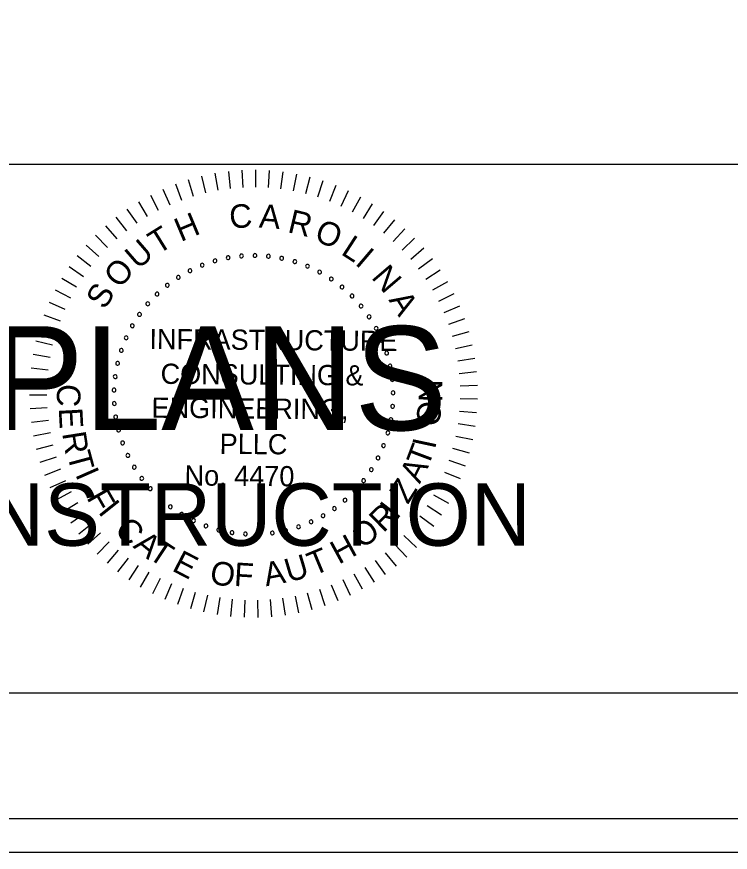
# Model space of a CAD drawing. Extents: x 967 to 1326, y 964 to 3704.
# Drawn here: x 1189.3 to 1212.88, y 3203.72 to 3231.36 of the extents above; entities that cross this region are included whole.
import ezdxf

# ---------------------------------------------------------------- set-up
doc = ezdxf.new("R2010")
doc.units = 0
for name, color, linetype in [('RD_SHT_Bndy', 7, 'Continuous'), ('RD_SHT_IplotShp', 7, 'Continuous'), ('RD_SHT_Misc1', 7, 'Continuous'), ('RD_SHT_Misc2', 7, 'Continuous'), ('RD_XS_TX_Station', 7, 'Continuous')]:
    doc.layers.add(name, color=color, linetype=linetype)

msp = doc.modelspace()

# ---------------------------------------------------------------- linework, layer by layer
at = {"layer": 'RD_SHT_Bndy'}
for p, q in [((996.114, 3226.486), (1323.886, 3226.486)), ((1323.886, 3208.983), (996.114, 3208.983))]:
    msp.add_line(p, q, dxfattribs=at)
at = {"layer": 'RD_SHT_IplotShp'}
for points in [[(967.409, 3203.72), (1326.285, 3203.72), (1326.285, 3423.72), (967.409, 3423.72)], [(988.525, 3204.84), (1326.285, 3204.84), (1326.285, 3422.6), (988.525, 3422.6)]]:
    msp.add_lwpolyline(points, close=True, dxfattribs=at)
at = {"layer": 'RD_SHT_Misc1'}
for p, q in [((1195.846, 3226.181), (1195.945, 3225.62)), ((1196.292, 3226.245), (1196.357, 3225.68)), ((1196.742, 3226.282), (1196.772, 3225.714)), ((1197.194, 3226.292), (1197.189, 3225.723)), ((1197.645, 3226.274), (1197.606, 3225.706)), ((1198.094, 3226.228), (1198.02, 3225.664)), ((1198.54, 3226.156), (1198.432, 3225.596)), ((1194.968, 3225.971), (1195.134, 3225.427)), ((1195.403, 3226.09), (1195.536, 3225.536)), ((1198.98, 3226.056), (1198.838, 3225.504)), ((1199.414, 3225.929), (1199.238, 3225.387)), ((1194.122, 3225.656), (1194.353, 3225.136)), ((1194.54, 3225.827), (1194.739, 3225.293)), ((1199.839, 3225.777), (1199.63, 3225.246)), ((1200.253, 3225.598), (1200.013, 3225.082)), ((1193.715, 3225.461), (1193.978, 3224.956)), ((1200.656, 3225.395), (1200.385, 3224.894)), ((1193.321, 3225.241), (1193.614, 3224.752)), ((1201.047, 3225.167), (1200.745, 3224.684)), ((1192.94, 3224.997), (1193.263, 3224.528)), ((1201.422, 3224.917), (1201.092, 3224.453)), ((1192.576, 3224.731), (1192.926, 3224.282)), ((1201.781, 3224.643), (1201.424, 3224.2)), ((1192.228, 3224.443), (1192.605, 3224.016)), ((1202.124, 3224.349), (1201.739, 3223.928)), ((1191.899, 3224.134), (1192.301, 3223.731)), ((1202.447, 3224.034), (1202.038, 3223.638)), ((1191.589, 3223.805), (1192.015, 3223.428)), ((1202.751, 3223.7), (1202.318, 3223.329)), ((1191.299, 3223.459), (1191.748, 3223.108)), ((1191.032, 3223.095), (1191.501, 3222.772)), ((1203.034, 3223.348), (1202.579, 3223.004)), ((1203.294, 3222.979), (1202.82, 3222.664)), ((1190.787, 3222.716), (1191.274, 3222.422)), ((1203.532, 3222.595), (1203.04, 3222.31)), ((1190.565, 3222.323), (1191.07, 3222.059)), ((1203.746, 3222.198), (1203.237, 3221.943)), ((1190.368, 3221.916), (1190.888, 3221.684)), ((1203.936, 3221.788), (1203.412, 3221.564)), ((1190.196, 3221.499), (1190.729, 3221.299)), ((1204.1, 3221.367), (1203.563, 3221.176)), ((1190.05, 3221.072), (1190.594, 3220.905)), ((1204.238, 3220.937), (1203.691, 3220.779)), ((1189.93, 3220.636), (1190.484, 3220.503)), ((1204.349, 3220.5), (1203.794, 3220.375)), ((1189.837, 3220.195), (1190.398, 3220.095)), ((1204.434, 3220.056), (1203.872, 3219.966)), ((1189.771, 3219.748), (1190.337, 3219.683)), ((1204.491, 3219.608), (1203.925, 3219.552)), ((1189.732, 3219.298), (1190.301, 3219.267)), ((1204.522, 3219.158), (1203.953, 3219.137)), ((1189.721, 3218.847), (1190.29, 3218.851)), ((1204.524, 3218.706), (1203.955, 3218.72)), ((1189.737, 3218.396), (1190.306, 3218.434)), ((1204.499, 3218.256), (1203.932, 3218.304)), ((1189.781, 3217.946), (1190.346, 3218.019)), ((1204.447, 3217.807), (1203.884, 3217.89)), ((1189.852, 3217.5), (1190.412, 3217.608)), ((1204.367, 3217.363), (1203.81, 3217.479)), ((1189.951, 3217.06), (1190.502, 3217.201)), ((1204.261, 3216.924), (1203.712, 3217.074)), ((1190.076, 3216.626), (1190.617, 3216.8)), ((1204.128, 3216.492), (1203.589, 3216.676)), ((1190.227, 3216.2), (1190.757, 3216.408)), ((1203.969, 3216.07), (1203.442, 3216.286)), ((1190.403, 3215.785), (1190.92, 3216.024)), ((1203.784, 3215.658), (1203.271, 3215.906)), ((1190.605, 3215.381), (1191.106, 3215.651)), ((1203.574, 3215.258), (1203.078, 3215.537)), ((1190.831, 3214.99), (1191.315, 3215.291)), ((1203.341, 3214.871), (1202.862, 3215.18)), ((1191.081, 3214.614), (1191.545, 3214.943)), ((1203.085, 3214.5), (1202.626, 3214.837)), ((1191.353, 3214.253), (1191.796, 3214.61)), ((1202.806, 3214.145), (1202.368, 3214.509)), ((1191.646, 3213.91), (1192.067, 3214.293)), ((1191.96, 3213.585), (1192.356, 3213.994)), ((1202.506, 3213.807), (1202.092, 3214.197)), ((1192.293, 3213.28), (1192.664, 3213.712)), ((1202.186, 3213.488), (1201.796, 3213.903)), ((1192.644, 3212.996), (1192.988, 3213.45)), ((1201.847, 3213.19), (1201.484, 3213.628)), ((1193.011, 3212.734), (1193.327, 3213.208)), ((1201.119, 3212.657), (1200.811, 3213.136)), ((1201.491, 3212.912), (1201.155, 3213.372)), ((1193.394, 3212.495), (1193.68, 3212.987)), ((1200.731, 3212.425), (1200.453, 3212.922)), ((1193.791, 3212.279), (1194.047, 3212.788)), ((1194.2, 3212.088), (1194.424, 3212.612)), ((1200.331, 3212.217), (1200.083, 3212.73)), ((1194.62, 3211.923), (1194.812, 3212.459)), ((1195.05, 3211.783), (1195.208, 3212.33)), ((1199.063, 3211.745), (1198.913, 3212.295)), ((1199.495, 3211.877), (1199.312, 3212.416)), ((1199.918, 3212.034), (1199.702, 3212.561)), ((1195.487, 3211.67), (1195.612, 3212.225)), ((1195.93, 3211.584), (1196.021, 3212.146)), ((1196.377, 3211.524), (1196.434, 3212.091)), ((1196.828, 3211.493), (1196.85, 3212.062)), ((1197.279, 3211.488), (1197.267, 3212.058)), ((1197.73, 3211.512), (1197.683, 3212.079)), ((1198.179, 3211.562), (1198.097, 3212.126)), ((1198.624, 3211.64), (1198.508, 3212.198))]:
    msp.add_line(p, q, dxfattribs=at)
for centre, start, end in [((1196.285, 3223.388), 10.6038, 190.6038), ((1196.285, 3223.388), 190.6038, 10.6038), ((1196.727, 3223.447), 5.0653, 185.0653), ((1196.727, 3223.447), 185.0653, 5.0653), ((1197.172, 3223.464), 359.5268, 179.5268), ((1197.172, 3223.464), 179.5268, 359.5268), ((1197.617, 3223.438), 173.9884, 353.9884), ((1197.617, 3223.438), 353.9884, 173.9884), ((1198.057, 3223.369), 168.4499, 348.4499), ((1198.057, 3223.369), 348.4499, 168.4499), ((1195.429, 3223.142), 21.6807, 201.6807), ((1195.429, 3223.142), 201.6807, 21.6807), ((1195.851, 3223.285), 16.1422, 196.1422), ((1195.851, 3223.285), 196.1422, 16.1422), ((1198.489, 3223.258), 162.9114, 342.9114), ((1198.489, 3223.258), 342.9114, 162.9114), ((1198.908, 3223.106), 157.373, 337.373), ((1198.908, 3223.106), 337.373, 157.373), ((1194.637, 3222.736), 32.7576, 212.7576), ((1195.023, 3222.958), 27.2191, 207.2191), ((1195.023, 3222.958), 207.2191, 27.2191), ((1199.31, 3222.914), 151.8345, 331.8345), ((1199.31, 3222.914), 331.8345, 151.8345), ((1194.274, 3222.478), 38.2961, 218.2961), ((1194.637, 3222.736), 212.7576, 32.7576), ((1199.692, 3222.684), 146.2961, 326.2961), ((1199.692, 3222.684), 326.2961, 146.2961), ((1193.937, 3222.186), 43.8345, 223.8345), ((1194.274, 3222.478), 218.2961, 38.2961), ((1200.05, 3222.419), 140.7576, 320.7576), ((1200.05, 3222.419), 320.7576, 140.7576), ((1193.937, 3222.186), 223.8345, 43.8345), ((1200.38, 3222.12), 135.2191, 315.2191), ((1200.38, 3222.12), 315.2191, 135.2191), ((1193.63, 3221.862), 49.373, 229.373), ((1193.63, 3221.862), 229.373, 49.373), ((1200.68, 3221.79), 129.6807, 309.6807), ((1200.68, 3221.79), 309.6807, 129.6807), ((1193.356, 3221.511), 54.9114, 234.9114), ((1193.356, 3221.511), 234.9114, 54.9114), ((1200.947, 3221.433), 124.1422, 304.1422), ((1200.947, 3221.433), 304.1422, 124.1422), ((1193.117, 3221.135), 60.4499, 240.4499), ((1193.117, 3221.135), 240.4499, 60.4499), ((1201.179, 3221.052), 118.6038, 298.6038), ((1201.179, 3221.052), 298.6038, 118.6038), ((1192.915, 3220.737), 65.9884, 245.9884), ((1192.915, 3220.737), 245.9884, 65.9884), ((1201.372, 3220.651), 113.0653, 293.0653), ((1201.372, 3220.651), 293.0653, 113.0653), ((1192.753, 3220.322), 71.5268, 251.5268), ((1192.753, 3220.322), 251.5268, 71.5268), ((1201.526, 3220.233), 107.5268, 287.5268), ((1201.526, 3220.233), 287.5268, 107.5268), ((1192.632, 3219.894), 77.0653, 257.0653), ((1192.632, 3219.894), 257.0653, 77.0653), ((1201.638, 3219.801), 101.9884, 281.9884), ((1201.638, 3219.801), 281.9884, 101.9884), ((1192.552, 3219.455), 82.6038, 262.6038), ((1192.552, 3219.455), 262.6038, 82.6038), ((1201.709, 3219.361), 96.4499, 276.4499), ((1201.709, 3219.361), 276.4499, 96.4499), ((1192.515, 3219.011), 88.1422, 268.1422), ((1192.515, 3219.011), 268.1422, 88.1422), ((1201.737, 3218.917), 90.9114, 270.9114), ((1201.737, 3218.917), 270.9114, 90.9114), ((1192.522, 3218.565), 93.6807, 273.6807), ((1192.522, 3218.565), 273.6807, 93.6807), ((1201.721, 3218.471), 85.373, 265.373), ((1201.721, 3218.471), 265.373, 85.373), ((1192.571, 3218.122), 99.2191, 279.2191), ((1192.571, 3218.122), 279.2191, 99.2191), ((1201.663, 3218.029), 79.8345, 259.8345), ((1201.663, 3218.029), 259.8345, 79.8345), ((1192.662, 3217.686), 104.7576, 284.7576), ((1192.662, 3217.686), 284.7576, 104.7576), ((1201.563, 3217.595), 74.2961, 254.2961), ((1201.563, 3217.595), 254.2961, 74.2961), ((1192.796, 3217.261), 110.2961, 290.2961), ((1192.796, 3217.261), 290.2961, 110.2961), ((1201.42, 3217.173), 68.7576, 248.7576), ((1201.42, 3217.173), 248.7576, 68.7576), ((1192.97, 3216.851), 115.8345, 295.8345), ((1192.97, 3216.851), 295.8345, 115.8345), ((1201.238, 3216.766), 63.2191, 243.2191), ((1201.238, 3216.766), 243.2191, 63.2191), ((1193.182, 3216.459), 121.373, 301.373), ((1193.182, 3216.459), 301.373, 121.373), ((1201.018, 3216.379), 57.6807, 237.6807), ((1201.018, 3216.379), 237.6807, 57.6807), ((1193.432, 3216.09), 126.9114, 306.9114), ((1193.432, 3216.09), 306.9114, 126.9114), ((1200.761, 3216.014), 52.1422, 232.1422), ((1200.761, 3216.014), 232.1422, 52.1422), ((1193.715, 3215.746), 132.4499, 312.4499), ((1193.715, 3215.746), 312.4499, 132.4499), ((1200.47, 3215.677), 46.6038, 226.6038), ((1200.47, 3215.677), 226.6038, 46.6038), ((1194.031, 3215.431), 137.9884, 317.9884), ((1194.031, 3215.431), 317.9884, 137.9884), ((1200.148, 3215.369), 41.0653, 221.0653), ((1200.148, 3215.369), 221.0653, 41.0653), ((1194.376, 3215.149), 143.5268, 323.5268), ((1194.376, 3215.149), 323.5268, 143.5268), ((1199.798, 3215.093), 35.5268, 215.5268), ((1199.798, 3215.093), 215.5268, 35.5268), ((1194.746, 3214.901), 149.0653, 329.0653), ((1194.746, 3214.901), 329.0653, 149.0653), ((1199.422, 3214.853), 29.9884, 209.9884), ((1199.422, 3214.853), 209.9884, 29.9884), ((1195.139, 3214.69), 154.6038, 334.6038), ((1195.139, 3214.69), 334.6038, 154.6038), ((1195.55, 3214.517), 160.1422, 340.1422), ((1195.55, 3214.517), 340.1422, 160.1422), ((1198.611, 3214.486), 18.9114, 198.9114), ((1198.611, 3214.486), 198.9114, 18.9114), ((1199.026, 3214.65), 24.4499, 204.4499), ((1199.026, 3214.65), 204.4499, 24.4499), ((1195.975, 3214.386), 165.6807, 345.6807), ((1195.975, 3214.386), 345.6807, 165.6807), ((1196.412, 3214.295), 171.2191, 351.2191), ((1196.412, 3214.295), 351.2191, 171.2191), ((1196.855, 3214.248), 356.7576, 176.7576), ((1196.855, 3214.248), 176.7576, 356.7576), ((1197.301, 3214.243), 2.2961, 182.2961), ((1197.301, 3214.243), 182.2961, 2.2961), ((1197.745, 3214.282), 7.8345, 187.8345), ((1197.745, 3214.282), 187.8345, 7.8345), ((1198.183, 3214.363), 13.373, 193.373), ((1198.183, 3214.363), 193.373, 13.373)]:
    msp.add_arc(centre, 0.0627, start, end, dxfattribs=at)
at = {"layer": 'RD_XS_TX_Station'}
msp.add_lwpolyline([(967.409, 3203.72), (1326.285, 3203.72), (1326.285, 3423.72), (967.409, 3423.72)], close=True, dxfattribs=at)

# ---------------------------------------------------------------- texts
at = {"layer": 'RD_SHT_Misc1'}
for s, height, rotation, p in [('C', 0.78, 4.7281, (1196.355, 3224.346)), ('A', 0.78, 355.6981, (1197.29, 3224.39)), ('H', 0.78, 22.7882, (1194.72, 3223.904)), ('R', 0.78, 346.6681, (1198.222, 3224.238)), ('T', 0.78, 31.8182, (1193.961, 3223.478)), ('O', 0.78, 337.638, (1199.096, 3223.972)), ('U', 0.78, 40.8482, (1193.306, 3222.976)), ('L', 0.78, 327.108, (1199.981, 3223.52)), ('I', 0.78, 319.578, (1200.451, 3223.182)), ('O', 0.78, 49.8782, (1192.707, 3222.341)), ('N', 0.78, 310.548, (1200.994, 3222.728)), ('S', 0.78, 58.9083, (1192.211, 3221.642)), ('A', 0.78, 301.5179, (1201.576, 3221.991)), ('INFRASTRUCTURE', 0.66873, 359.5268, (1193.682, 3220.367)), ('CONSULTING &', 0.66873, 359.5268, (1194.051, 3219.217)), ('N', 0.78, 89.2085, (1203.359, 3218.604)), ('C', 0.78, 267.025, (1190.646, 3219.227)), ('ENGINEERING,', 0.66873, 359.5268, (1193.751, 3218.095)), ('O', 0.78, 83.2085, (1203.26, 3217.786)), ('E', 0.78, 273.025, (1190.685, 3218.408)), ('R', 0.78, 279.025, (1190.799, 3217.583)), ('PLLC', 0.6687, 359.5268, (1196.002, 3216.9)), ('T', 0.78, 69.3954, (1202.891, 3216.428)), ('I', 0.78, 77.9093, (1203.121, 3217.032)), ('T', 0.78, 285.025, (1190.955, 3216.878)), ('I', 0.78, 293.7713, (1191.221, 3216.225)), ('No. 4470', 0.6687, 359.5268, (1194.843, 3215.855)), ('A', 0.78, 63.3954, (1202.616, 3215.888)), ('Z', 0.78, 57.3954, (1202.224, 3215.206)), ('F', 0.78, 299.7713, (1191.589, 3215.455)), ('I', 0.78, 308.5268, (1191.965, 3214.973)), ('R', 0.78, 44.5268, (1201.415, 3214.267)), ('I', 0.78, 52.3339, (1201.856, 3214.69)), ('C', 0.78, 314.5268, (1192.496, 3214.346)), ('O', 0.78, 38.5268, (1200.73, 3213.731)), ('A', 0.78, 320.5268, (1193.115, 3213.822)), ('H', 0.78, 28.5268, (1199.942, 3213.23)), ('T', 0.78, 326.5268, (1193.602, 3213.478)), ('E', 0.78, 332.5268, (1194.394, 3213.051)), ('T', 0.78, 22.5268, (1199.108, 3212.856)), ('U', 0.78, 16.5268, (1198.288, 3212.638)), ('O', 0.78, 350.5268, (1195.647, 3212.614)), ('F', 0.78, 356.5268, (1196.465, 3212.532)), ('A', 0.78, 10.5268, (1197.537, 3212.517))]:
    msp.add_text(s, height=height, rotation=rotation, dxfattribs=at).set_placement(p)
at = {"layer": 'RD_SHT_Misc2'}
for s, height, p in [('FINAL PLANS', 3.4375, (1174.145, 3217.685)), ('NOT FOR CONSTRUCTION', 2.0625, (1170.901, 3213.86))]:
    msp.add_text(s, height=height, dxfattribs=at).set_placement(p)

doc.saveas('drawing.dxf')
